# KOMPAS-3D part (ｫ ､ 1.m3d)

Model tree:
1. Эскиз:1
2. Операция выдавливания:1
     Расстояние 1 = 20
3. Эскиз:2
4. Операция выдавливания:2
     Расстояние 1 = 400
5. Эскиз:3
6. Вырезать элемент выдавливания:1
     Расстояние 1 = 70
7. Эскиз:4
8. Вырезать элемент выдавливания:2
     Расстояние 1 = 2
9. Эскиз:5
10. Эскиз:11
11. Вырезать элемент выдавливания:7
     Расстояние 1 = 30
12. Операция выдавливания:3
     Расстояние 1 = 16.96
13. Эскиз:13
14. Вырезать элемент выдавливания:9
     Расстояние 1 = 70
15. Эскиз:14
16. Вырезать элемент выдавливания:10
     Расстояние 1 = 80
